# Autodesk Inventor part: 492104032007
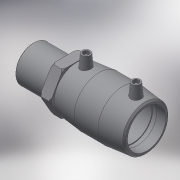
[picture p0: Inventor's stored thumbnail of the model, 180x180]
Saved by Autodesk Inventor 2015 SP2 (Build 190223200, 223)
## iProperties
Created: 2017-06
Part Number: 492104032007
Material: Generic
Description: PLASSON Male Transition Coupler 32 x 3/4"
Document SubType Name: Modeling
Designer: KIM
Mass: 88.9441 g
Surface Area: 290.345 cm^2
Volume: 88.9441 cm^3
Density: 1 g/cm^3
Appearance: Default
Author: KIM
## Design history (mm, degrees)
derived "492104.ipt"
feature "Solid1::492104.ipt"
tag "TaggingFeature1"
body "Solid1"
other parameters: "d0" = 81, "d1" = 32, "d2" = 44, "d3" = 39, "d4" = 27, "d5" = 39.6, "d6" = 30.4, "d7" = 32, "d8" = 168 deg, "d10" = 15.6, "d11" = 5.2, "d29" = 42, "d30" = 14, "d31" = 28.35, "d34" = 5 deg, "d41" = 4, "d42" = 14, "d43" = 0, "d48" = 3, "d49" = 0, "d57" = 19, "d58" = 26.441, "d59" = 21.1528, "d60" = 26.1, "d61" = 44, "d62" = 0.52882, "d65" = 1.32, "d70" = 0.1, "d71" = 29, "d72" = 7.25, "d73" = 15.6, "d75" = 0, "d_" = 32, "L_1" = 39, "D_1" = 44, "A_" = 42, "d_2" = 12, "L_2" = 29, "D_" = 19, "R_" = 26.441
